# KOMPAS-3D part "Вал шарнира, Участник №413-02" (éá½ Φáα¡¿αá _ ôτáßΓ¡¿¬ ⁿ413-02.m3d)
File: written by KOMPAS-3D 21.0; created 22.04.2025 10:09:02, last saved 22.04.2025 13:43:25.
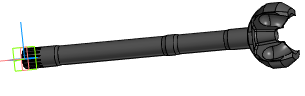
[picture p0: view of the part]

Document properties: Автор: adm; Полное имя файла: D:\OLIMPGM-2025№1\Г-413\№2\Вал шарнира _ Участник №413-02.m3d

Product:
- Part/product: Вал шарнира  | designation Участник №413-02
    Материал: Сталь 27ХГР ГОСТ 4543-2016 (density 7850 kg/m3)
    Масса: 9.111738
    Форматы листов документа: A1

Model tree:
1. Эскиз:2
2. Элемент вращения:1
     Угол 1 = 360
3. Скругление:1  (with: Элемент вращения:1)
     Радиус = 25
4. Эскиз:3
5. Элемент выдавливания:1
     Расстояние 1 = 71; Расстояние 2 = 71
6. Зеркальный массив:1
7. Экземпляр ( 1 )
8. Экземпляр ( 2 )  (with: Элемент выдавливания:1)
9. Эскиз:5  (with: Элемент вращения:1)
10. Элемент вращения:2
     Угол 1 = 360
11. Фаска:1  (with: Элемент вращения:1)
     Угол = 45; Длина 1 = 3; Длина 2 = 3
12. Эскиз:6
13. Плоскость под углом:1
     Угол = 11.25
14. Эскиз:7  (with: Элемент вращения:1)
15. Элемент по траектории:1
16. Массив по концентрической сетке:1  (with: Элемент по траектории:1, Плоскость под углом:1, Эскиз:6, Эскиз:7)  (16 pattern instances)
     Шаг 2 = 360
17. Эскиз:8
18. Плоскость под углом:2
     Угол = 45
19. Плоскость под углом:3
     Угол = 45
20. Смещенная плоскость:1
     Расстояние = 4
21. Смещенная плоскость:2
     Расстояние = 4
22. Смещенная плоскость:3
     Расстояние = 4
23. Смещенная плоскость:4
     Расстояние = 4
24. Элемент вращения:3
     Угол 1 = 360
25. Разрезать:2
26. Булева операция:1
27. Булева операция:2
28. Смещенная плоскость:5
29. Разрезать:3
30. Булева операция:3
31. Эскиз:9
32. Элемент вращения:4
     Угол 1 = 360
33. Эскиз:10
34. Параллельная плоскость:1
35. Эскиз:11
36. Элемент по траектории:2
37. Ось через точку по направлению:1
38. Эскиз:12
39. Элемент вращения:5
     Угол 1 = 360
40. Зеркальный массив:2  (with: Экземпляр ( 1 ), Экземпляр ( 2 ), Элемент вращения:5, Элемент по траектории:2)
41. Зеркальный массив:3  (with: Экземпляр ( 1 ), Экземпляр ( 2 ), Зеркальный массив:2, Элемент вращения:5, Элемент по траектории:2)
42. Скругление:2  (with: Разрезать:3)
     Радиус = 4
43. Эскиз:13  (with: Разрезать:3)
44. Элемент выдавливания:3
     Расстояние 1 = 46.25; Расстояние 2 = 46.25
45. Эскиз:14
46. Элемент вращения:6
     Угол 1 = 360
47. Скругление:3  (with: Разрезать:3)  (labels: Сталь 27ХГР ГОСТ 4543-2016)
     Радиус = 5

Expressions: 92.5/2; 62/2; 50.38/2; 360/16; 610-93.5+47.5; 610-93.5+67
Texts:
  Участник №413-02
